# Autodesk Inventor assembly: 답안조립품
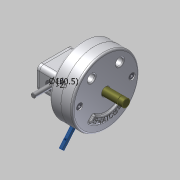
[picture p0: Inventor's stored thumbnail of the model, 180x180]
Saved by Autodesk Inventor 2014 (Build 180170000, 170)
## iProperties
Created: 2015-04
Part Number: 답안조립품
Document SubType Name: Assembly
Designer: Administrator
Author: Administrator
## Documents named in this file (15)
- C:\Documents and Settings\Administrator\바탕 화면\350406V1024\답안조립품.iam
- C:\Documents and Settings\Administrator\바탕 화면\350406V1024\본체.ipt
- C:\Documents and Settings\Administrator\바탕 화면\350406V1024\커버.ipt
- C:\Documents and Settings\Administrator\바탕 화면\350406V1024\M 10 x 35.ipt
- C:\Documents and Settings\Administrator\바탕 화면\350406V1024\축.ipt
- C:\Documents and Settings\Administrator\바탕 화면\350406V1024\커버2.ipt
- C:\Documents and Settings\Administrator\바탕 화면\350406V1024\멈춤링.ipt
- C:\Documents and Settings\Administrator\바탕 화면\350406V1024\베어링62_22.ipt
- C:\Documents and Settings\Administrator\바탕 화면\350406V1024\M 5 x 12.ipt
- C:\Documents and Settings\Administrator\바탕 화면\350406V1024\슬라이더2.ipt
- C:\Documents and Settings\Administrator\바탕 화면\350406V1024\슬라이더.ipt
- C:\Documents and Settings\Administrator\바탕 화면\350406V1024\평행핀.ipt
- C:\Documents and Settings\Administrator\바탕 화면\350406V1024\슬라이더3.ipt
- C:\Documents and Settings\Administrator\바탕 화면\350406V1024\가변 스프링.ipt
- C:\Documents and Settings\Administrator\바탕 화면\350406V1024\부시.ipt
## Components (6 placed, 4 different names)
1. M 10 x 35:1
2. M 10 x 35:2
3. M 5 x 12:1
4. M 5 x 12:2
5. KS B 1320 B B 5 x  20:1 — 플러쉬:1
6. 가변 스프링:1
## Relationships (1: Flush 1)
- 플러쉬:1 [Flush]: KS B 1320 B B 5 x  20:1
